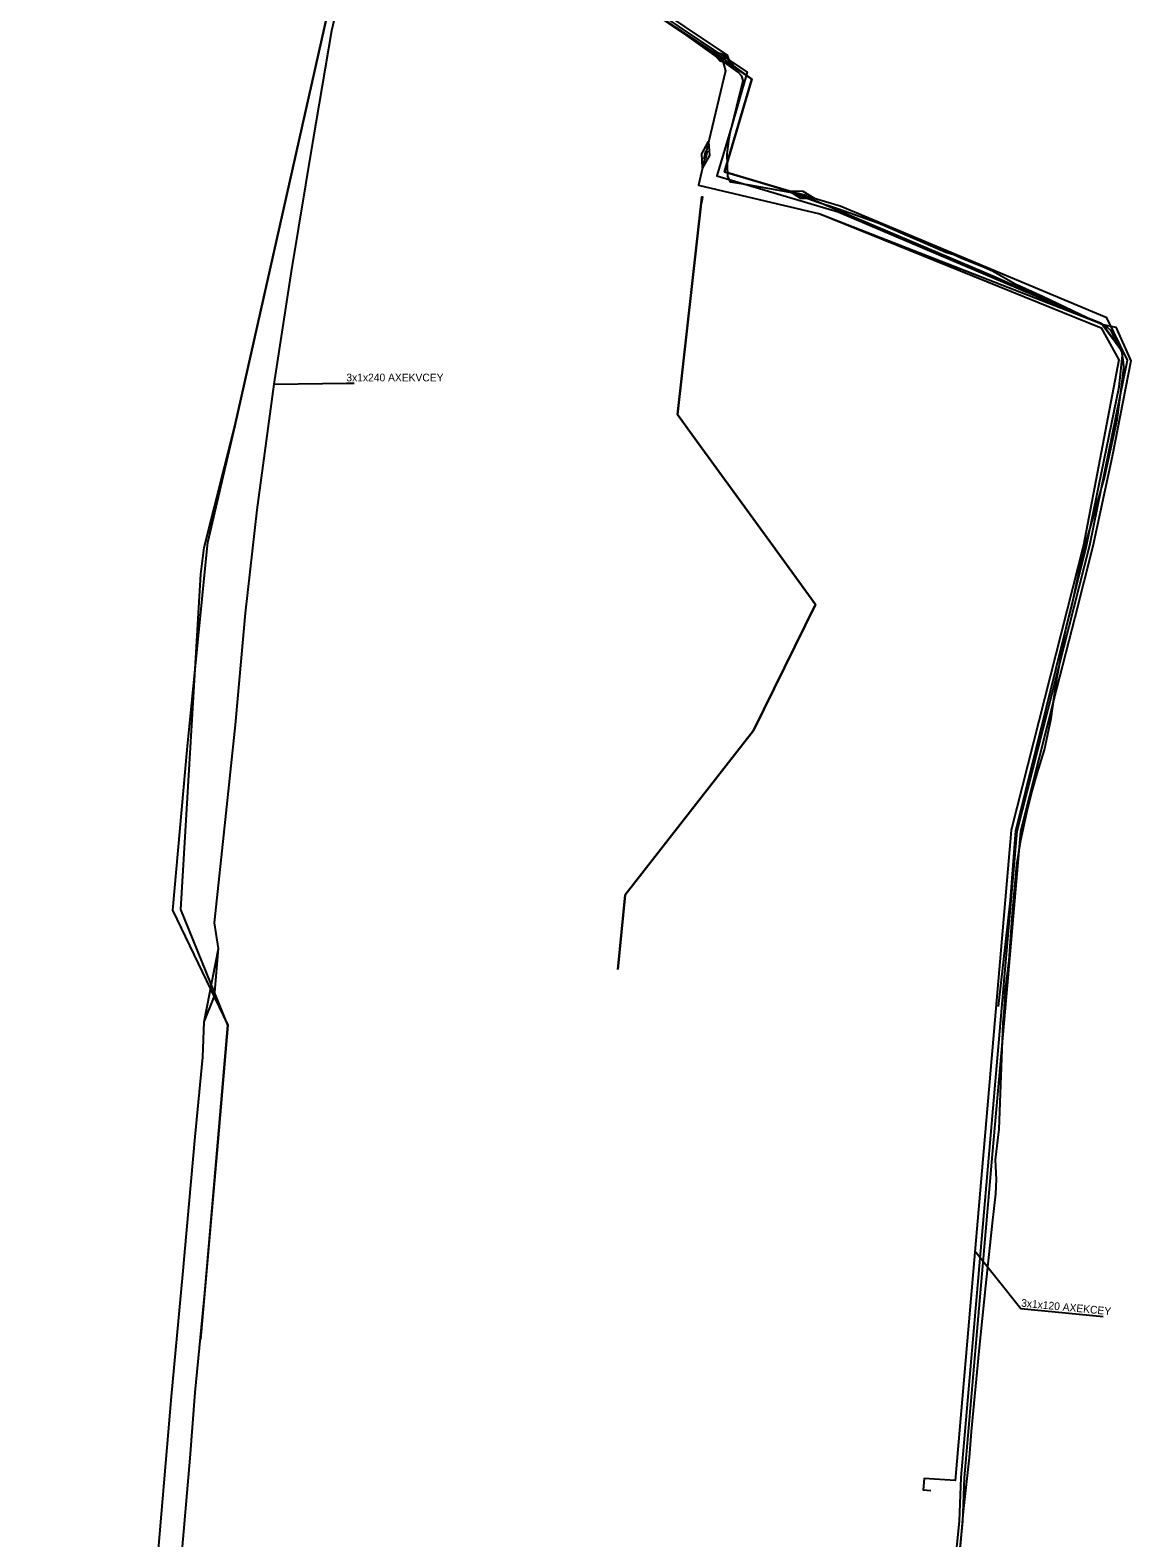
# Model space of a CAD drawing. Extents: x -739895 to -737975, y -1046419 to -1045728.
# Drawn here: x -739766.2 to -739622.9, y -1046129.2 to -1045932.9 of the extents above; entities that cross this region are included whole.
import ezdxf

# ---------------------------------------------------------------- set-up
doc = ezdxf.new("R2010")
doc.units = 0
for name, color, linetype in [('TR_SPOJKOVISTE_VN', 7, 'Continuous'), ('TRASA_KABELU_VN_PROVOZ', 7, 'Continuous'), ('TRASA_KABELU_VN_VYRAZENO', 7, 'Continuous'), ('VN_KABELOVE_VEDENI_PROVOZ', 7, 'Continuous'), ('VN_KABELOVE_VEDENI_VYRAZENO', 7, 'Continuous'), ('VN_POPIS_USEKU', 7, 'Continuous'), ('VN_SPOJKA_KONCOVKA', 7, 'Continuous')]:
    doc.layers.add(name, color=color, linetype=linetype)

msp = doc.modelspace()

# ---------------------------------------------------------------- linework, layer by layer
at = {"layer": 'TR_SPOJKOVISTE_VN'}
for points in [[(-739674.64, -1045937.5), (-739676.37, -1045936.96), (-739677.56, -1045935.58), (-739675.82, -1045936.12), (-739674.64, -1045937.5)], [(-739678.63, -1045950.87), (-739678.74, -1045949.05), (-739677.86, -1045947.45), (-739677.76, -1045949.27), (-739678.63, -1045950.87)], [(-739664.05, -1045954.87), (-739665.87, -1045954.85), (-739667.4, -1045953.86), (-739665.58, -1045953.89), (-739664.05, -1045954.87)]]:
    msp.add_lwpolyline(points, dxfattribs=at)
at = {"layer": 'TRASA_KABELU_VN_PROVOZ'}
for points in [[(-739749.46, -1046130.72), (-739747.74, -1046110.8), (-739746.29, -1046094.93), (-739744.66, -1046077.01), (-739743.67, -1046066.64), (-739743.52, -1046062.06), (-739742.17, -1046058.69), (-739741.63, -1046052.49), (-739742.18, -1046049.16), (-739740.75, -1046035.69), (-739739.45, -1046023.37), (-739738.11, -1046008.85), (-739736.59, -1045995.37), (-739734.39, -1045979.01), (-739732.13, -1045964.36), (-739729.33, -1045947.32), (-739726.88, -1045932.97), (-739724.75, -1045923.86), (-739723.84, -1045921.69), (-739722.8, -1045920.27), (-739722.13, -1045918.92), (-739722.13, -1045917.36), (-739720.61, -1045907.24)], [(-739715.51, -1045910.8), (-739712.01, -1045913.09), (-739711.27, -1045913.58), (-739692.68, -1045925.59), (-739676.1, -1045936.54)], [(-739645.38, -1046133.85), (-739644.68, -1046125.8), (-739643.92, -1046118.75), (-739643.65, -1046115.38), (-739642.66, -1046104.93), (-739641.77, -1046096.41), (-739640.89, -1046088.26), (-739640.46, -1046084.44), (-739640.4, -1046082.56), (-739640.5, -1046080), (-739640.02, -1046076), (-739639.52, -1046062.18), (-739639.34, -1046060.26), (-739639.25, -1046058.15), (-739638.75, -1046054.04), (-739638.32, -1046047.88), (-739637.75, -1046041.6), (-739637.23, -1046038.37), (-739636.45, -1046034.8), (-739635.73, -1046032), (-739635.08, -1046029.72), (-739634.14, -1046026.61), (-739633.25, -1046022.55), (-739632.66, -1046018.17), (-739631.35, -1046010.93), (-739630.54, -1046007.73), (-739629.15, -1046001.11), (-739627.17, -1045994.12), (-739626.31, -1045991.2), (-739624.68, -1045983.66), (-739624.06, -1045979.09), (-739623.81, -1045976.92), (-739623.85, -1045976.06), (-739624.09, -1045974.79), (-739625.47, -1045972.1), (-739625.92, -1045971.67), (-739626.84, -1045971.08), (-739628.57, -1045970.39), (-739634.38, -1045967.63), (-739637.95, -1045966.02), (-739640.89, -1045964.32), (-739641.99, -1045963.83), (-739644.79, -1045962.69), (-739645.93, -1045962.17), (-739646.97, -1045961.9), (-739650.95, -1045960.16), (-739655.79, -1045958.08), (-739661.08, -1045956.2), (-739663.71, -1045955.34), (-739667.23, -1045954.08), (-739672.55, -1045953.11), (-739675.01, -1045952.74), (-739675.37, -1045951.93), (-739675.44, -1045949.04), (-739675.17, -1045947.06), (-739675.04, -1045946.35), (-739673.37, -1045939.5), (-739673.54, -1045938.91), (-739674.01, -1045938.39), (-739679.47, -1045934.49), (-739684.15, -1045931.17)], [(-739676.1, -1045936.54), (-739675.66, -1045938.25), (-739678.25, -1045949.16), (-739679.18, -1045953.11), (-739663.39, -1045956.87), (-739626.67, -1045971.16), (-739623.93, -1045974.85)], [(-739640.14, -1046060.04), (-739638.58, -1046046.22), (-739637.88, -1046037.17), (-739628.66, -1046000.06), (-739624.41, -1045979.38), (-739623.93, -1045974.85)]]:
    msp.add_lwpolyline(points, dxfattribs=at)
at = {"layer": 'TRASA_KABELU_VN_VYRAZENO'}
for points in [[(-739766.16, -1046344.68), (-739766.11, -1046342.56), (-739763.2, -1046311.95), (-739761.68, -1046295.97), (-739758.86, -1046269.57), (-739755.83, -1046234.36), (-739752.98, -1046201.83), (-739751.88, -1046193.29), (-739749.29, -1046164.38), (-739748.1, -1046150.99), (-739745.33, -1046118.84), (-739744.68, -1046110.28), (-739743.44, -1046097.32), (-739741.73, -1046077.71), (-739740.43, -1046062.48), (-739746.54, -1046047.42), (-739743.96, -1046003.75), (-739743.52, -1046000.31), (-739739.5, -1045984.46), (-739726.54, -1045926.7), (-739726.07, -1045924.21)], [(-739676.1, -1045936.54), (-739672.21, -1045939.3), (-739675.79, -1045951.38), (-739665.72, -1045954.37), (-739640.88, -1045964.93), (-739626.55, -1045971.28), (-739623.93, -1045974.81)], [(-739678.76, -1045955.07), (-739681.9, -1045982.99), (-739679.45, -1045986.42), (-739669.56, -1046000), (-739663.95, -1046007.7), (-739672.01, -1046024.11), (-739688.71, -1046045.5), (-739689.65, -1046055.23)]]:
    msp.add_lwpolyline(points, dxfattribs=at)
at = {"layer": 'VN_KABELOVE_VEDENI_PROVOZ'}
msp.add_line((-739677.81, -1045935.55), (-739711.06, -1045913.27), dxfattribs=at)
for points in [[(-739712.48, -1045911.45), (-739711.06, -1045912.31), (-739703.12, -1045917.63), (-739675.42, -1045936.19), (-739675.24, -1045936.79), (-739672.85, -1045938.41), (-739674.93, -1045945.64), (-739676.79, -1045951.92), (-739661, -1045956.6), (-739626.51, -1045971.24), (-739624.84, -1045971.6), (-739622.9, -1045976), (-739625.32, -1045988.46), (-739627.85, -1046000.1), (-739630.21, -1046009.4), (-739632.57, -1046018.7), (-739637.28, -1046037.28), (-739639.1, -1046058.3), (-739640.93, -1046079.32), (-739642.75, -1046100.36), (-739644.58, -1046121.39), (-739644.83, -1046127.08), (-739645.75, -1046136.49)], [(-739749.46, -1046130.72), (-739747.74, -1046110.8), (-739746.29, -1046094.93), (-739744.66, -1046077.01), (-739743.67, -1046066.64), (-739743.52, -1046062.06), (-739741.63, -1046052.49), (-739742.18, -1046049.16), (-739740.75, -1046035.69), (-739739.45, -1046023.37), (-739738.11, -1046008.85), (-739736.59, -1045995.37), (-739734.39, -1045979.01), (-739732.13, -1045964.36), (-739729.33, -1045947.32), (-739726.88, -1045932.97), (-739724.75, -1045923.86)], [(-739677.81, -1045935.55), (-739676.1, -1045936.69), (-739675.66, -1045938.25), (-739678.25, -1045949.16)], [(-739678.25, -1045949.16), (-739679.18, -1045953.11), (-739663.39, -1045956.87), (-739626.75, -1045971.68), (-739624.45, -1045975.88), (-739629.07, -1046000), (-739638.47, -1046037.08), (-739645.75, -1046121.76), (-739649.79, -1046121.48), (-739649.91, -1046122.98), (-739648.94, -1046123.06)]]:
    msp.add_lwpolyline(points, dxfattribs=at)
at = {"layer": 'VN_KABELOVE_VEDENI_VYRAZENO'}
for points in [[(-739665.72, -1045954.37), (-739675.79, -1045951.38), (-739672.21, -1045939.3), (-739675.59, -1045937.04), (-739675.76, -1045936.44), (-739712.2, -1045912.02)], [(-739726.54, -1045926.7), (-739739.5, -1045984.46), (-739743.09, -1045999.69), (-739743.12, -1046000), (-739745.75, -1046026.62), (-739747.62, -1046047.51), (-739740.43, -1046062.48), (-739741.73, -1046077.71), (-739743.97, -1046103.38)], [(-739689.65, -1046055.23), (-739688.71, -1046045.5), (-739672.01, -1046024.11), (-739663.95, -1046007.7), (-739669.56, -1046000), (-739679.45, -1045986.42), (-739681.9, -1045982.99), (-739678.76, -1045955.07)], [(-739648.67, -1046166.52), (-739648.29, -1046161.31), (-739648.03, -1046157.32), (-739647.28, -1046149.57), (-739646.26, -1046140.16), (-739646.15, -1046136.47), (-739645.22, -1046127.05), (-739644.98, -1046121.37), (-739637.68, -1046037.21), (-739628.24, -1046000), (-739623.34, -1045975.92), (-739626.04, -1045970.37), (-739660.73, -1045955.84), (-739665.72, -1045954.37)]]:
    msp.add_lwpolyline(points, dxfattribs=at)
at = {"layer": 'VN_POPIS_USEKU'}
for points in [[(-739734.39, -1045979.01), (-739725, -1045978.91), (-739724, -1045978.91)], [(-739643.21, -1046091.85), (-739637.23, -1046099.36), (-739626.5, -1046100.4)]]:
    msp.add_lwpolyline(points, dxfattribs=at)
at = {"layer": 'VN_SPOJKA_KONCOVKA'}
for points in [[(-739678.19, -1045935.2), (-739677.34, -1045935.75), (-739677.44, -1045935.9), (-739678.29, -1045935.35)], [(-739678.04, -1045948.69), (-739678.27, -1045949.68), (-739678.45, -1045949.63), (-739678.22, -1045948.65)], [(-739678.84, -1045955.45), (-739678.75, -1045954.62), (-739678.67, -1045954.63), (-739678.76, -1045955.46), (-739678.78, -1045955.46), (-739678.7, -1045954.68), (-739678.73, -1045954.68), (-739678.81, -1045955.46)], [(-739665.26, -1045954.59), (-739666.23, -1045954.31), (-739666.18, -1045954.14), (-739665.21, -1045954.42)]]:
    msp.add_lwpolyline(points, close=True, dxfattribs=at)

# ---------------------------------------------------------------- texts
at = {"layer": 'VN_POPIS_USEKU'}
msp.add_text('3x1x240 AXEKVCEY', height=1, dxfattribs=at).set_placement((-739725, -1045978.66))
msp.add_text('3x1x120 AXEKCEY', height=1, rotation=354.4932, dxfattribs=at).set_placement((-739637.21, -1046099.11))

doc.saveas('drawing.dxf')
